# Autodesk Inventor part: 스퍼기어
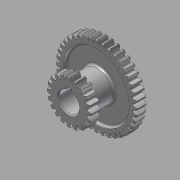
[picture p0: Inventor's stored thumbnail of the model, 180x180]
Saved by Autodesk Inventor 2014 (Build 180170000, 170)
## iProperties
Created: 2015-09
Part Number: 스퍼기어
Material: 강철, 연강
Document SubType Name: Modeling
Designer: mduedu
Density: 7.86 g/cm^3
Mass: 345.726 g
Surface Area: 225.641 cm^2
Volume: 43.9855 cm^3
Appearance: 강철
Author: mduedu
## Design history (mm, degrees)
sketch "스케치1"
  geometry: C1 r 38 at (0, 0); C2 r 40 at (0, 0); C3 r 35.5 at (0, 0); 1 further point
  constraints: 3 centre point, 3 coincident
  dimensions: "d0" = 76 diameter of C1; "d2" = 2 radial gap between concentric circles of C2 C1; "d3" = 71 diameter of C3 (computed from d0)
extrude "돌출1" new body sketch "스케치1" stored distance "d4" = 10; taper "d5" = 0 deg
sketch "스케치2"
  geometry: L1 (0, 35.5)-(0, -35.5); L2 (0, 0)-(40, 0); L3 (0, 0.57)-(39.996, 0.57); L4 (0, 1.57)-(39.969, 1.57); L5 (0, 2.07)-(39.946, 2.07); A1 r 35.5 centre (0, 0) between (0, 35.5) and (0, -35.5) reference; A2 r 40 centre (0, 0) between (40, 0) and (39.946, 2.07) reference; A3 r 9.234 centre (34.93, -7.149) between (39.996, 0.57) and (35.44, 2.07); A4 r 9.234 centre (34.93, 7.149) between (35.44, -2.07) and (39.996, -0.57); A5 r 40 centre (0, 0) between (39.996, -0.57) and (39.996, 0.57); A6 r 35.5 centre (0, 0) between (35.44, -2.07) and (35.44, 2.07); 4 further points
  constraints: 16 point on circle, 10 end point, 6 point on line, 4 centre point, 3 coincident, 3 parallel, 3 symmetric about line, 2 midpoint, 1 perpendicular, 1 vertical, 3 other
  dimensions: "d6" = 0.5 distance between parallel lines of L4 L5; "d8" = 1 distance between parallel lines of L3 L4; "d9" = 1.57 distance between parallel lines of L2 L4
extrude "돌출2" join sketch "스케치2" distance "d10" = 5; taper "d12" = 0 deg; dims "d11" = 5, "d13" = 0
fillet "모깎기1" dims "d17" = 0.5
chamfer "모따기1" distance "d21" = 1; stored, may be unused: second distance "d22" = 2, angle "d23" = 45 deg
sketch "스케치3"
  geometry: C1 r 32.5 at (0, 0); C2 r 15 at (0, 0); 1 further point
  constraints: 2 centre point, 2 coincident
  dimensions: "d27" = 65 diameter of C1; "d28" = 30 diameter of C2
extrude "돌출3" cut sketch "스케치3" distance "d29" = 3; taper "d30" = 0 deg
fillet "모깎기2" dims "d31" = 2
node "작업 평면2"
  node "작업 평면1"
sketch "스케치4"
  geometry: C1 r 15 at (0, 0) reference; 1 further point
extrude "돌출4" join sketch "스케치4" stored distance "d34" = 3; taper "d35" = 0 deg
sketch "스케치5"
  geometry: C1 r 17.5 at (0, 0); C2 r 20 at (0, 0); C3 r 22 at (0, 0); 1 further point
  constraints: 3 centre point, 3 coincident
  dimensions: "d36" = 40 diameter of C2; "d38" = 2 radial gap between concentric circles of C2 C3; "d39" = 35 diameter of C1 (= d36 - 2.5 x d38)
extrude "돌출6" join sketch "스케치5" distance "d46" = 10; taper "d47" = 0 deg
sketch "스케치6"
  geometry: L1 (0, 0)-(0, 22); L2 (-17.5, 0)-(17.5, 0); L3 (-0.57, 0)-(-0.57, 21.993); L4 (-1.57, 0)-(-1.57, 21.944); L5 (-2.07, 0)-(-2.07, 21.902); A1 r 22 centre (0, 0) between (0, 22) and (-0.57, 21.993) reference; A2 r 17.5 centre (0, 0) between (-17.5, 0) and (17.5, 0) reference; A3 r 9.431 centre (7.348, 16.868) between (-0.57, 21.993) and (-2.07, 17.377); A4 r 9.431 centre (-7.348, 16.868) between (2.07, 17.377) and (0.57, 21.993); A5 r 17.5 centre (0, 0) between (2.07, 17.377) and (-2.07, 17.377); A6 r 22 centre (0, 0) between (0.57, 21.993) and (-0.57, 21.993); 4 further points
  constraints: 16 point on circle, 10 end point, 5 point on line, 4 centre point, 3 coincident, 3 symmetric about line, 2 parallel, 2 perpendicular, 1 midpoint, 1 vertical, 3 other
  dimensions: "d40" = 0.5 distance between parallel lines of L4 L5; "d42" = 1 distance between parallel lines of L3 L4; "d43" = 1.57 distance between parallel lines of L1 L4
extrude "돌출5" join sketch "스케치6" distance "d44" = 10; taper "d45" = 0 deg
fillet "모깎기3" dims "d48" = 0.5
chamfer "모따기2" distance "d49" = 1; stored, may be unused: second distance "d50" = 2, angle "d51" = 45 deg
sketch "스케치7"
  geometry: C1 r 10 at (0, 0); 1 further point
  constraints: 1 centre point, 1 coincident
  dimensions: "d55" = 20 diameter of C1
extrude "돌출7" cut sketch "스케치7" stored distance "d56" = 10; taper "d57" = 0 deg
sketch "스케치8"
  geometry: L1 (-9.539, -3)-(-12.8, -3); L2 (-12.8, -3)-(-12.8, 3); L3 (-12.8, 3)-(-9.539, 3); L4 (-9.539, 3)-(-9.539, -3); A1 r 10 centre (0, 0) between (-9.539, -3) and (-9.539, 3) reference; 2 further points
  constraints: 8 end point, 3 point on circle, 2 parallel, 1 horizontal, 1 horizontal alignment, 1 perpendicular
  dimensions: "d58" = 6 distance of L1.end L2.end; "d60" = 22.8 distance from line of point (10, 0) L2
extrude "돌출8" cut sketch "스케치8" stored distance "d61" = 10; taper "d62" = 0 deg
chamfer "모따기3" distance "d63" = 1; stored, may be unused: second distance "d64" = 2, angle "d65" = 45 deg
fillet "모깎기4" dims "d66" = 2
node "솔리드1"
pattern_circular "원형 패턴3" dims "d25" = 360 deg
mirror "대칭1"
pattern_circular "원형 패턴4" dims "d53" = 360 deg
other parameters: "d32" = 5, "d33" = 42
